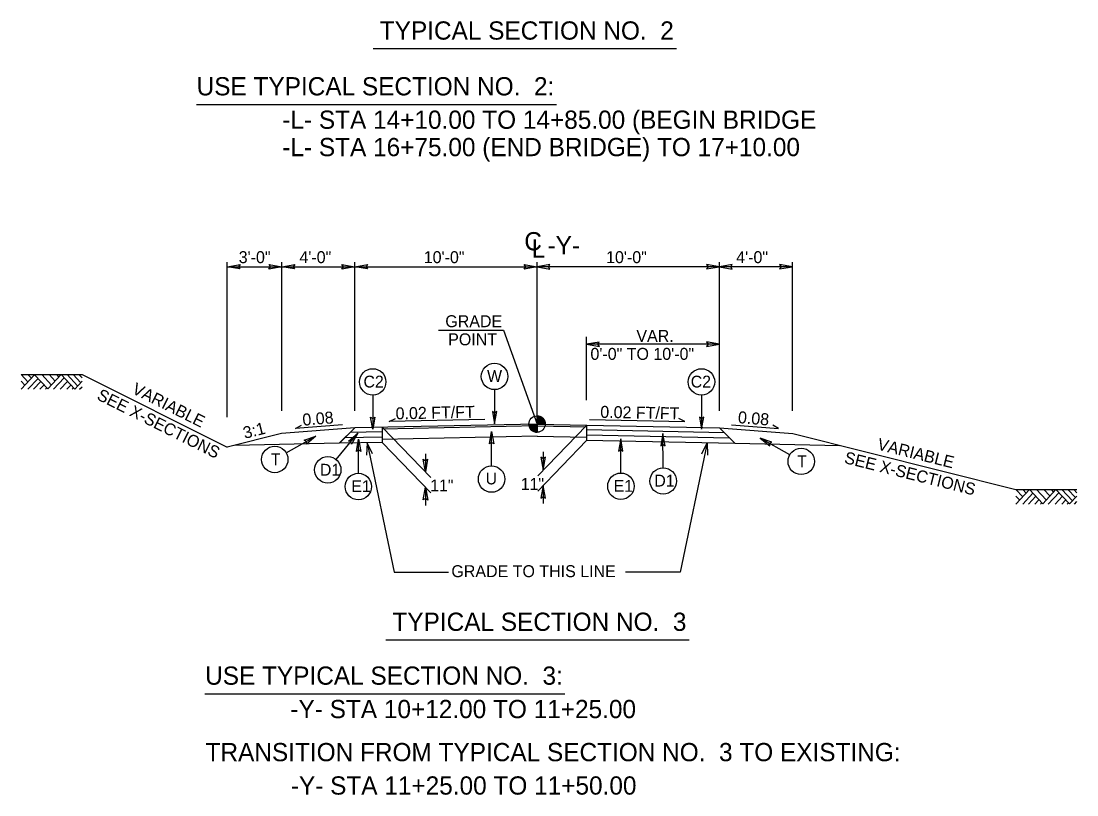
# Model space of a CAD drawing. Extents: x 1901984 to 1902132, y 194049 to 194156.
# Drawn here: x 1901991.3 to 1902049.2, y 194052.5 to 194095 of the extents above; entities that cross this region are included whole.
import ezdxf

# ---------------------------------------------------------------- set-up
doc = ezdxf.new("R2010")
doc.units = 0
for name, color, linetype in [('Old_Level_1', 7, 'Continuous'), ('Old_Level_11', 7, 'Continuous'), ('Old_Level_2', 7, 'Continuous'), ('Old_Level_20', 7, 'Continuous'), ('Old_Level_3', 7, 'Continuous'), ('Scratch_Level_3', 7, 'Continuous')]:
    doc.layers.add(name, color=color, linetype=linetype)

# ---------------------------------------------------------------- blocks, each defined once
blk = doc.blocks.new('TERMINATOR')
at = {"layer": 'Scratch_Level_3'}
blk.add_lwpolyline([(-0.469, 0.081), (0, 0), (-0.471, -0.083), (-0.411, 0)], close=True, dxfattribs=at)

msp = doc.modelspace()

# ---------------------------------------------------------------- linework, layer by layer
at = {"layer": 'Old_Level_1'}
for p, q in [((1902002.561, 194073.237), (1902002.561, 194081.737)), ((1902005.561, 194073.585), (1902005.561, 194081.737)), ((1902009.561, 194073.585), (1902009.561, 194081.737)), ((1902019.561, 194073.372), (1902019.561, 194081.737)), ((1902029.561, 194073.585), (1902029.561, 194081.737)), ((1902033.561, 194073.585), (1902033.561, 194081.737)), ((1902002.561, 194081.487), (1902005.561, 194081.487)), ((1902005.561, 194081.487), (1902009.561, 194081.487)), ((1902009.561, 194081.487), (1902019.561, 194081.487)), ((1902029.561, 194081.487), (1902019.561, 194081.487)), ((1902033.561, 194081.487), (1902029.561, 194081.487)), ((1902022.27, 194074.174), (1902022.27, 194077.645)), ((1902029.561, 194077.238), (1902022.27, 194077.238)), ((1901994.604, 194075.573), (1902002.561, 194071.595)), ((1902019.561, 194072.862), (1902009.561, 194072.662)), ((1902011.453, 194072.999), (1902011.786, 194073.166)), ((1902016.685, 194073.109), (1902011.453, 194072.999)), ((1902019.111, 194072.862), (1902019.561, 194072.862)), ((1902019.56, 194072.412), (1902019.561, 194072.862)), ((1902019.561, 194072.862), (1902019.56, 194072.412)), ((1902019.561, 194073.208), (1902019.561, 194073.372)), ((1902019.561, 194072.862), (1902019.561, 194073.312)), ((1902020.011, 194072.862), (1902019.561, 194072.862)), ((1902019.561, 194072.862), (1902029.561, 194072.662)), ((1902022.437, 194073.109), (1902027.669, 194072.999)), ((1902027.669, 194072.999), (1902027.336, 194073.166)), ((1902005.543, 194072.34), (1902002.561, 194071.595)), ((1902009.561, 194072.662), (1902005.543, 194072.34)), ((1902008.897, 194072.828), (1902006.317, 194072.622)), ((1902006.317, 194072.622), (1902006.64, 194072.808)), ((1902009.561, 194072.662), (1902008.711, 194071.811)), ((1902009.561, 194072.662), (1902008.753, 194071.854)), ((1902011.061, 194072.441), (1902009.306, 194072.406)), ((1902019.561, 194072.758), (1902011.061, 194072.588)), ((1902011.061, 194072.692), (1902011.061, 194071.858)), ((1902011.061, 194072.692), (1902013.739, 194069.925)), ((1902019.561, 194072.758), (1902022.27, 194072.703)), ((1902022.27, 194072.791), (1902019.592, 194070.024)), ((1902022.27, 194072.791), (1902022.27, 194071.957)), ((1902022.27, 194072.557), (1902029.816, 194072.406)), ((1902029.561, 194072.662), (1902033.579, 194072.34)), ((1902029.561, 194072.662), (1902030.411, 194071.811)), ((1902030.225, 194072.828), (1902032.805, 194072.622)), ((1902032.805, 194072.622), (1902032.482, 194072.808)), ((1902033.579, 194072.34), (1902045.822, 194069.279)), ((1902008.711, 194071.811), (1902002.967, 194071.696)), ((1902011.061, 194071.858), (1902008.711, 194071.811)), ((1902011.061, 194072.15), (1902009.008, 194072.109)), ((1902010.237, 194071.842), (1902011.724, 194064.737)), ((1902019.561, 194072.195), (1902011.061, 194072.025)), ((1902011.061, 194071.858), (1902013.739, 194069.091)), ((1902019.561, 194072.195), (1902022.27, 194072.141)), ((1902022.27, 194071.957), (1902019.592, 194069.19)), ((1902022.27, 194072.266), (1902030.114, 194072.109)), ((1902022.27, 194071.974), (1902030.411, 194071.811)), ((1902028.888, 194071.837), (1902027.398, 194064.737)), ((1902030.411, 194071.811), (1902036.155, 194071.696)), ((1902013.437, 194071.237), (1902013.437, 194070.237)), ((1902019.894, 194071.336), (1902019.894, 194070.336)), ((1902013.437, 194069.403), (1902013.437, 194068.403)), ((1902019.894, 194069.503), (1902019.894, 194068.503)), ((1902011.724, 194064.737), (1902014.708, 194064.737)), ((1902027.398, 194064.737), (1902024.414, 194064.737))]:
    msp.add_line(p, q, dxfattribs=at)
for points in [[(1901991.262, 194075.573), (1901994.604, 194075.573)], [(1902019.113, 194072.862), (1902019.113, 194072.813)], [(1902019.122, 194072.862), (1902019.122, 194072.76)], [(1902019.131, 194072.862), (1902019.131, 194072.728)], [(1902019.14, 194072.862), (1902019.14, 194072.701)], [(1902019.149, 194072.862), (1902019.149, 194072.68)], [(1902019.158, 194072.862), (1902019.158, 194072.661)], [(1902019.167, 194072.862), (1902019.167, 194072.644)], [(1902019.176, 194072.862), (1902019.176, 194072.628)], [(1902019.185, 194072.862), (1902019.185, 194072.614)], [(1902019.194, 194072.862), (1902019.194, 194072.601)], [(1902019.203, 194072.862), (1902019.203, 194072.589)], [(1902019.212, 194072.862), (1902019.212, 194072.578)], [(1902019.221, 194072.862), (1902019.221, 194072.567)], [(1902019.23, 194072.862), (1902019.23, 194072.557)], [(1902019.239, 194072.862), (1902019.239, 194072.547)], [(1902019.248, 194072.862), (1902019.248, 194072.538)], [(1902019.257, 194072.862), (1902019.257, 194072.53)], [(1902019.266, 194072.862), (1902019.266, 194072.522)], [(1902019.275, 194072.862), (1902019.275, 194072.514)], [(1902019.284, 194072.862), (1902019.284, 194072.507)], [(1902019.293, 194072.862), (1902019.293, 194072.5)], [(1902019.302, 194072.862), (1902019.302, 194072.494)], [(1902019.311, 194072.862), (1902019.311, 194072.488)], [(1902019.32, 194072.862), (1902019.32, 194072.482)], [(1902019.329, 194072.862), (1902019.329, 194072.476)], [(1902019.338, 194072.862), (1902019.338, 194072.471)], [(1902019.347, 194072.862), (1902019.347, 194072.466)], [(1902019.356, 194072.862), (1902019.356, 194072.461)], [(1902019.365, 194072.862), (1902019.365, 194072.457)], [(1902019.374, 194072.862), (1902019.374, 194072.453)], [(1902019.383, 194072.862), (1902019.383, 194072.449)], [(1902019.392, 194072.862), (1902019.392, 194072.445)], [(1902019.401, 194072.862), (1902019.401, 194072.441)], [(1902019.41, 194072.862), (1902019.41, 194072.438)], [(1902019.419, 194072.862), (1902019.419, 194072.435)], [(1902019.428, 194072.862), (1902019.428, 194072.432)], [(1902019.437, 194072.862), (1902019.437, 194072.43)], [(1902019.446, 194072.862), (1902019.446, 194072.427)], [(1902019.455, 194072.862), (1902019.455, 194072.425)], [(1902019.464, 194072.862), (1902019.464, 194072.423)], [(1902019.473, 194072.862), (1902019.473, 194072.421)], [(1902019.482, 194072.862), (1902019.482, 194072.419)], [(1902019.491, 194072.862), (1902019.491, 194072.418)], [(1902019.5, 194072.862), (1902019.5, 194072.416)], [(1902019.509, 194072.862), (1902019.509, 194072.415)], [(1902019.518, 194072.862), (1902019.518, 194072.414)], [(1902019.527, 194072.862), (1902019.527, 194072.413)], [(1902019.536, 194072.862), (1902019.536, 194072.413)], [(1902019.545, 194072.862), (1902019.545, 194072.412)], [(1902019.554, 194072.862), (1902019.554, 194072.412), (1902019.554, 194072.412)], [(1902019.565, 194073.312), (1902019.565, 194073.312), (1902019.565, 194072.862)], [(1902019.574, 194073.312), (1902019.574, 194072.862)], [(1902019.583, 194073.311), (1902019.583, 194072.862)], [(1902019.592, 194073.311), (1902019.592, 194072.862)], [(1902019.601, 194073.31), (1902019.601, 194072.862)], [(1902019.61, 194073.309), (1902019.61, 194072.862)], [(1902019.619, 194073.308), (1902019.619, 194072.862)], [(1902019.628, 194073.307), (1902019.628, 194072.862)], [(1902019.637, 194073.306), (1902019.637, 194072.862)], [(1902019.646, 194073.304), (1902019.646, 194072.862)], [(1902019.655, 194073.302), (1902019.655, 194072.862)], [(1902019.664, 194073.3), (1902019.664, 194072.862)], [(1902019.673, 194073.298), (1902019.673, 194072.862)], [(1902019.682, 194073.295), (1902019.682, 194072.862)], [(1902019.691, 194073.293), (1902019.691, 194072.862)], [(1902019.7, 194073.29), (1902019.7, 194072.862)], [(1902019.709, 194073.287), (1902019.709, 194072.862)], [(1902019.718, 194073.284), (1902019.718, 194072.862)], [(1902019.727, 194073.28), (1902019.727, 194072.862)], [(1902019.736, 194073.276), (1902019.736, 194072.862)], [(1902019.745, 194073.272), (1902019.745, 194072.862)], [(1902019.754, 194073.268), (1902019.754, 194072.862)], [(1902019.763, 194073.264), (1902019.763, 194072.862)], [(1902019.772, 194073.259), (1902019.772, 194072.862)], [(1902019.781, 194073.254), (1902019.781, 194072.862)], [(1902019.79, 194073.249), (1902019.79, 194072.862)], [(1902019.799, 194073.244), (1902019.799, 194072.862)], [(1902019.808, 194073.238), (1902019.808, 194072.862)], [(1902019.817, 194073.232), (1902019.817, 194072.862)], [(1902019.826, 194073.225), (1902019.826, 194072.862)], [(1902019.835, 194073.219), (1902019.835, 194072.862)], [(1902019.844, 194073.212), (1902019.844, 194072.862)], [(1902019.853, 194073.204), (1902019.853, 194072.862)], [(1902019.862, 194073.196), (1902019.862, 194072.862)], [(1902019.871, 194073.188), (1902019.871, 194072.862)], [(1902019.88, 194073.179), (1902019.88, 194072.862)], [(1902019.889, 194073.17), (1902019.889, 194072.862)], [(1902019.898, 194073.16), (1902019.898, 194072.862)], [(1902019.907, 194073.149), (1902019.907, 194072.862)], [(1902019.916, 194073.138), (1902019.916, 194072.862)], [(1902019.925, 194073.126), (1902019.925, 194072.862)], [(1902019.934, 194073.113), (1902019.934, 194072.862)], [(1902019.943, 194073.099), (1902019.943, 194072.862)], [(1902019.952, 194073.084), (1902019.952, 194072.862)], [(1902019.961, 194073.068), (1902019.961, 194072.862)], [(1902019.97, 194073.049), (1902019.97, 194072.862)], [(1902019.979, 194073.028), (1902019.979, 194072.862)], [(1902019.988, 194073.003), (1902019.988, 194072.862)], [(1902019.997, 194072.972), (1902019.997, 194072.862)], [(1902020.006, 194072.926), (1902020.006, 194072.862)], [(1902010.528, 194071.228), (1902010.234, 194071.837), (1902010.207, 194071.162)], [(1902028.594, 194071.228), (1902028.888, 194071.837), (1902028.915, 194071.162)], [(1902045.822, 194069.279), (1902049.164, 194069.279)]]:
    msp.add_lwpolyline(points, dxfattribs=at)
msp.add_circle((1902019.56, 194072.862), 0.45, dxfattribs=at)
for start, end in [(179.99048, 269.99048), (359.99048, 89.99048)]:
    msp.add_arc((1902019.56, 194072.862), 0.45, start, end, dxfattribs=at)
at = {"layer": 'Old_Level_11'}
for p, q in [((1902010.577, 194093.446), (1902027.203, 194093.446)), ((1902000.887, 194090.388), (1902020.63, 194090.388)), ((1901991.262, 194075.573), (1901991.637, 194075.17)), ((1901991.262, 194074.768), (1901992.004, 194075.565)), ((1901991.262, 194075.211), (1901991.468, 194074.989)), ((1901991.636, 194074.768), (1901992.19, 194075.364)), ((1901991.637, 194075.573), (1901991.824, 194075.372)), ((1901991.945, 194074.768), (1901992.346, 194075.197)), ((1901992.004, 194075.565), (1901992.728, 194074.786)), ((1901992.395, 194075.573), (1901992.928, 194075)), ((1901992.728, 194074.786), (1901993.459, 194075.572)), ((1901992.793, 194075.573), (1901993.126, 194075.214)), ((1901993.038, 194074.768), (1901993.624, 194075.396)), ((1901993.195, 194075.573), (1901993.328, 194075.43)), ((1901993.408, 194074.768), (1901993.808, 194075.197)), ((1901993.459, 194075.572), (1901994.2, 194074.776)), ((1901993.781, 194075.573), (1901994.361, 194074.95)), ((1901994.114, 194075.573), (1901994.528, 194075.129)), ((1901994.2, 194074.776), (1901994.604, 194075.211)), ((1901994.434, 194075.573), (1901994.604, 194075.39)), ((1901992.292, 194074.768), (1901992.519, 194075.011)), ((1901992.603, 194074.768), (1901992.674, 194074.844)), ((1901993.774, 194074.768), (1901993.991, 194075.001)), ((1901994.069, 194074.768), (1901994.138, 194074.842)), ((1901994.47, 194074.768), (1901994.604, 194074.911)), ((1902017.226, 194074.75), (1902017.226, 194072.876)), ((1902010.546, 194074.448), (1902010.546, 194072.574)), ((1902028.576, 194074.448), (1902028.576, 194072.574)), ((1902008.537, 194070.915), (1902009.723, 194072.366)), ((1902017.064, 194070.574), (1902017.064, 194072.448)), ((1902026.473, 194070.466), (1902026.464, 194072.34)), ((1902005.804, 194071.278), (1902007.434, 194072.202)), ((1902009.76, 194070.162), (1902009.769, 194072.036)), ((1902024.154, 194070.177), (1902024.145, 194072.051)), ((1902033.418, 194071.174), (1902031.787, 194072.098)), ((1902045.822, 194069.279), (1902046.197, 194068.876)), ((1902045.822, 194068.474), (1902046.564, 194069.271)), ((1902045.822, 194068.917), (1902046.028, 194068.695)), ((1902046.196, 194068.474), (1902046.75, 194069.07)), ((1902046.197, 194069.279), (1902046.384, 194069.078)), ((1902046.505, 194068.474), (1902046.906, 194068.903)), ((1902046.564, 194069.271), (1902047.288, 194068.492)), ((1902046.955, 194069.279), (1902047.488, 194068.706)), ((1902047.288, 194068.492), (1902048.019, 194069.278)), ((1902047.353, 194069.279), (1902047.686, 194068.92)), ((1902047.598, 194068.474), (1902048.184, 194069.102)), ((1902047.755, 194069.279), (1902047.888, 194069.136)), ((1902047.968, 194068.474), (1902048.368, 194068.903)), ((1902048.019, 194069.278), (1902048.76, 194068.482)), ((1902048.341, 194069.279), (1902048.921, 194068.656)), ((1902048.674, 194069.279), (1902049.088, 194068.835)), ((1902048.76, 194068.482), (1902049.164, 194068.917)), ((1902048.994, 194069.279), (1902049.164, 194069.096)), ((1902046.852, 194068.474), (1902047.079, 194068.717)), ((1902047.163, 194068.474), (1902047.234, 194068.55)), ((1902048.334, 194068.474), (1902048.551, 194068.707)), ((1902048.629, 194068.474), (1902048.698, 194068.548)), ((1902049.03, 194068.474), (1902049.164, 194068.617)), ((1902011.269, 194061.03), (1902027.895, 194061.03)), ((1902001.331, 194058.077), (1902021.074, 194058.077))]:
    msp.add_line(p, q, dxfattribs=at)
for points in [[(1902017.11, 194073.548), (1902017.226, 194072.876), (1902017.345, 194073.551), (1902017.226, 194073.465)], [(1902010.661, 194073.246), (1902010.546, 194072.574), (1902010.426, 194073.249), (1902010.546, 194073.163)], [(1902028.461, 194073.246), (1902028.576, 194072.574), (1902028.696, 194073.249), (1902028.576, 194073.163)], [(1902009.208, 194071.919), (1902009.723, 194072.366), (1902009.388, 194071.768), (1902009.35, 194071.91)], [(1902016.949, 194071.776), (1902017.064, 194072.448), (1902017.184, 194071.773), (1902017.064, 194071.858)], [(1902026.583, 194071.669), (1902026.464, 194072.34), (1902026.348, 194071.665), (1902026.467, 194071.751)], [(1902006.793, 194071.972), (1902007.434, 194072.202), (1902006.906, 194071.765), (1902006.921, 194071.912)], [(1902009.65, 194071.365), (1902009.769, 194072.036), (1902009.885, 194071.361), (1902009.766, 194071.447)], [(1902024.264, 194071.38), (1902024.145, 194072.051), (1902024.029, 194071.376), (1902024.148, 194071.462)], [(1902032.428, 194071.868), (1902031.787, 194072.098), (1902032.316, 194071.661), (1902032.3, 194071.808)]]:
    msp.add_lwpolyline(points, close=True, dxfattribs=at)
for centre in [(1902010.545, 194075.173), (1902017.226, 194075.475), (1902028.576, 194075.173), (1902005.173, 194070.921), (1902034.048, 194070.817), (1902008.078, 194070.354), (1902017.064, 194069.848), (1902009.757, 194069.437), (1902024.157, 194069.452), (1902026.476, 194069.741)]:
    msp.add_circle(centre, 0.725, dxfattribs=at)
at = {"layer": 'Old_Level_3'}
for p, q in [((1902014.153, 194078.016), (1902017.717, 194078.016)), ((1902017.717, 194078.016), (1902019.561, 194072.862))]:
    msp.add_line(p, q, dxfattribs=at)

# ---------------------------------------------------------------- block references
at = {"layer": 'Old_Level_1', "xscale": 1.5}
for p, yscale, rotation in [((1902002.561, 194081.487), 1.5, 180), ((1902005.561, 194081.487), 1.5, 180), ((1902005.561, 194081.487), 1.5, 180), ((1902009.561, 194081.487), 1.5, 180), ((1902019.561, 194081.487), -1.5, 180), ((1902029.561, 194081.487), -1.5, 180), ((1902022.27, 194077.238), -1.5, 180), ((1902013.437, 194070.237), 1.5, -90), ((1902019.894, 194070.336), -1.5, -90), ((1902013.437, 194069.403), 1.5, 90), ((1902019.894, 194069.503), -1.5, 90)]:
    msp.add_blockref('TERMINATOR', p, dxfattribs=dict(at, yscale=yscale, rotation=rotation))
for p, yscale in [((1902005.561, 194081.487), 1.5), ((1902009.561, 194081.487), 1.5), ((1902019.561, 194081.487), 1.5), ((1902029.561, 194081.487), -1.5), ((1902033.561, 194081.487), -1.5), ((1902033.561, 194081.487), -1.5), ((1902029.561, 194077.238), -1.5)]:
    msp.add_blockref('TERMINATOR', p, dxfattribs=dict(at, yscale=yscale))

# ---------------------------------------------------------------- texts
at = {"layer": 'Old_Level_1'}
for s, p in [('3\'-0" ', (1902003.196, 194081.685)), ('10\'-0"', (1902013.345, 194081.685)), ('10\'-0"', (1902023.345, 194081.685)), ('4\'-0"', (1902030.479, 194081.685)), ('VAR.', (1902025.005, 194077.367)), ('0\'-0" TO 10\'-0"', (1902022.486, 194076.383)), ('GRADE TO THIS LINE', (1902014.859, 194064.469))]:
    msp.add_text(s, height=0.656, dxfattribs=at).set_placement(p)
for s, rotation, p in [('4\'-0"', 360, (1902006.525, 194081.685)), ('SEE X-SECTIONS', 333.43495, (1901995.367, 194074.24)), ('VARIABLE', 333.43495, (1901997.293, 194074.569)), ('3:1', 14.03624, (1902003.527, 194072.049)), ('VARIABLE', 345.96376, (1902038.175, 194071.471)), ('SEE X-SECTIONS', 345.96376, (1902036.367, 194070.732))]:
    msp.add_text(s, height=0.656, rotation=rotation, dxfattribs=at).set_placement(p)
at = {"layer": 'Old_Level_11'}
for s, height, p in [('TYPICAL SECTION NO.  2', 1, (1902010.933, 194093.94)), ('USE TYPICAL SECTION NO.  2:', 1, (1902000.887, 194090.882)), ('-L- STA 14+10.00 TO 14+85.00 (BEGIN BRIDGE', 1, (1902005.587, 194089.05)), ('-L- STA 16+75.00 (END BRIDGE) TO 17+10.00', 1, (1902005.587, 194087.55)), ('GRADE', 0.656, (1902014.526, 194078.174)), ('POINT', 0.656, (1902014.684, 194077.18)), ('TYPICAL SECTION NO.  3', 1, (1902011.625, 194061.524)), ('USE TYPICAL SECTION NO.  3:', 1, (1902001.355, 194058.571)), ('-Y- STA 10+12.00 TO 11+25.00', 1, (1902006.031, 194056.739)), ('TRANSITION FROM TYPICAL SECTION NO.  3 TO EXISTING:', 1, (1902001.379, 194054.378)), ('-Y- STA 11+25.00 TO 11+50.00', 1, (1902006.055, 194052.547))]:
    msp.add_text(s, height=height, dxfattribs=at).set_placement(p)
at = {"layer": 'Old_Level_2'}
msp.add_text('C', height=1, dxfattribs=at).set_placement((1902018.859, 194082.388))
for s, height, rotation, p in [('L', 1, 359.9469, (1902019.261, 194081.984)), ('-Y-', 1, 359.9469, (1902020.13, 194082.167)), ('0.08', 0.656, 4.57392, (1902006.718, 194072.771)), ('0.02 FT/FT', 0.656, 1.19158, (1902011.808, 194073.118)), ('0.02 FT/FT', 0.656, 358.80842, (1902023.021, 194073.207)), ('0.08', 0.656, 355.42608, (1902030.557, 194072.919))]:
    msp.add_text(s, height=height, rotation=rotation, dxfattribs=at).set_placement(p)
at = {"layer": 'Old_Level_20'}
for s, height, p in [('W', 0.649, (1902016.817, 194075.169)), ('C2', 0.6491, (1902010.039, 194074.867)), ('C2', 0.6491, (1902027.987, 194074.867)), ('T', 0.649, (1902033.824, 194070.499)), ('D1', 0.6491, (1902007.653, 194070.034)), ('U', 0.649, (1902016.737, 194069.555)), ('D1', 0.6491, (1902025.992, 194069.438)), ('E1', 0.6491, (1902009.374, 194069.134)), ('11"', 0.6491, (1902013.699, 194069.173)), ('11"', 0.6491, (1902018.667, 194069.256)), ('E1', 0.6491, (1902023.761, 194069.149))]:
    msp.add_text(s, height=height, dxfattribs=at).set_placement(p)
msp.add_text('T', height=0.649, rotation=360, dxfattribs=at).set_placement((1902004.959, 194070.604))

doc.saveas('drawing.dxf')
